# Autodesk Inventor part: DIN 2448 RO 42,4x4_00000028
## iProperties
Created: 2006-02
Part Number: DIN 2448 RO 42,4x4_00000028
Material: Default
Document SubType Name: Modeling
Designer: FranzK
Stock Number: DIN 2448 RO 42,4x4
Mass: 421.965 g
Surface Area: 2123.47 cm^2
Volume: 421.965 cm^3
Density: 1 g/cm^3
G_L: 890.000 mm
G_W: 42.400 mm
G_H: 42.400 mm
AFG_Item: 42.4 x 4
CSToolsMass: 0.4
CSToolsVolume: 421965.0
CSToolsArea: 2123.0
Author: FranzK
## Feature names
1. AFG_Detailed_DIN 2448 RO 42,4x4_00000028 [Extrusion]
2. AFG_Simplified_DIN 2448 RO 42,4x4_00000028 [Extrusion]
3. AFG_StartExtrusion_1 [Extrusion]
4. AFG_StartExtrusion_2 [Extrusion]
